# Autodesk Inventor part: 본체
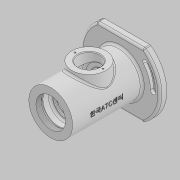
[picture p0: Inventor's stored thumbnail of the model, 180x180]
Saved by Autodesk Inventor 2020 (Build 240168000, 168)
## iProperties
Created: 2022-05
Part Number: 본체
Material: 일반
Document SubType Name: Modeling
Designer: User
Density: 1 g/cm^3
Appearance: 기본값
Author: User
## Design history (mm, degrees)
sketch "스케치1"
  geometry: L1 (-33.985, 47)-(33.985, 47); L2 (-33.985, -47)-(33.985, -47); A1 r 58 centre (0, 0) between (33.985, -47) and (33.985, 47); A2 r 58 centre (0, 0) between (-33.985, 47) and (-33.985, -47); 2 further points
  constraints: 4 end point, 4 point on circle, 3 vertical alignment, 2 centre point, 2 coincident, 2 horizontal, 1 midpoint
  dimensions: "d0" = 94 distance between parallel lines of L2 L1; "d2" = 58 radius of A1
extrude "돌출1" new body sketch "스케치1" distance "d3" = 10; taper "d4" = 0 deg
sketch "스케치2"
  geometry: C1 r 36 at (0, 0); 1 further point
  constraints: 1 centre point, 1 coincident
  dimensions: "d5" = 72 diameter of C1
extrude "돌출2" join sketch "스케치2" distance "d6" = 3; taper "d7" = 0 deg
sketch "스케치3"
  geometry: C1 r 32 at (0, 0); 1 further point
  constraints: 1 centre point, 1 coincident
  dimensions: "d8" = 64 diameter of C1
extrude "돌출3" join sketch "스케치3" distance "d9" = 102; taper "d10" = 0 deg
sketch "스케치4"
  geometry: L1 (0, 0)-(48, 0); L2 (0, 0)-(36.77, 30.854); L3 (0, 0)-(-36.77, -30.854); L4 (-48, 0)-(0, 0); C1 r 4 at (36.77, 30.854); C2 r 4 at (-36.77, -30.854); A1 r 48 centre (0, 0) between (48, 0) and (36.77, 30.854); A2 r 48 centre (0, 0) between (48, 0) and (36.77, 30.854); A3 r 52 centre (0, 0) between (52, 0) and (39.834, 33.425); A4 r 44 centre (0, 0) between (44, 0) and (33.706, 28.283); A5 r 4 centre (48, 0) between (44, 0) and (52, 0); A6 r 4 centre (36.77, 30.854) between (39.834, 33.425) and (33.706, 28.283); A7 r 48 centre (0, 0) between (-48, 0) and (-36.77, -30.854); A8 r 52 centre (0, 0) between (-52, 0) and (-39.834, -33.425); A9 r 44 centre (0, 0) between (-44, 0) and (-33.706, -28.283); A10 r 4 centre (-48, 0) between (-44, 0) and (-52, 0); A11 r 4 centre (-36.77, -30.854) between (-39.834, -33.425) and (-33.706, -28.283); A12 r 48 centre (0, 0) between (48, 0) and (36.77, 30.854); A13 r 50.25 centre (0, 0) between (50.25, 0) and (38.494, 32.3); A14 r 45.75 centre (0, 0) between (45.75, 0) and (35.047, 29.408); A15 r 2.25 centre (48, 0) between (45.75, 0) and (50.25, 0); A16 r 2.25 centre (36.77, 30.854) between (38.494, 32.3) and (35.047, 29.408); A17 r 48 centre (0, 0) between (-48, 0) and (-36.77, -30.854); A18 r 50.25 centre (0, 0) between (-50.25, 0) and (-38.494, -32.3); A19 r 45.75 centre (0, 0) between (-45.75, 0) and (-35.047, -29.408); A20 r 2.25 centre (-48, 0) between (-45.75, 0) and (-50.25, 0); A21 r 2.25 centre (-36.77, -30.854) between (-38.494, -32.3) and (-35.047, -29.408); 5 further points
  constraints: 44 point on circle, 23 centre point, 16 tangent, 8 end point, 7 coincident, 2 horizontal
  dimensions: "d11" = 96 diameter of A1; "d12" = 40 deg angle of L1 L2; "d13" = 4 radius of A6; "d14" = 40 deg angle of L3 L4; "d15" = 4 radius of A10; "d16" = 2.25 radius of A16; "d18" = 2.25 radius of A20; "d25" = 8 diameter of C1; "d26" = 8 diameter of C2
extrude "돌출4" cut sketch "스케치4" distance "d19" = 4.4; taper "d20" = 0 deg
extrude "돌출5" cut sketch "스케치4" distance "d21" = 4.4; taper "d22" = 0 deg
extrude "돌출6" cut sketch "스케치4" extent not by distance; stored distance "d23" = 0; taper "d24" = 0 deg
extrude "돌출7" cut sketch "스케치4" extent not by distance; stored distance "d27" = 102; taper "d28" = 0 deg
sketch "스케치5"
  geometry: L1 (-36, -3)-(36, -3) reference; L2 (0, -3)-(0, 104); L3 (0, 104)-(24, 104); L4 (24, 104)-(24, 101); L5 (24, 101)-(22.5, 101); L6 (22.5, 101)-(22.5, 93); L7 (19.5, 90)-(18.5, 90); L8 (17.5, 89)-(17.5, 87.75); L9 (17.5, 87.75)-(18.5, 87.75); L10 (18.5, 87.75)-(18.5, 86); L11 (18.5, 86)-(17.5, 86); L12 (17.5, 86)-(17.5, 76); L13 (18.5, 75)-(24, 75); L14 (27, 72)-(27, 40); L15 (24, 37)-(18.5, 37); L16 (17.5, 36)-(17.5, 26.6); L17 (16.9, 26)-(15, 26); L18 (15, 26)-(15, 24); L19 (12, 21)-(11, 21); L20 (11, 21)-(11, 18.3); L21 (11, 18.3)-(14.5, 18.3); L22 (15, 17.8)-(15, 11.7); L23 (15.404, 11)-(18.456, 11); L24 (20.897, 9.744)-(30, -3); L25 (18.5, 90)-(17.5, 89); L26 (18.5, 75)-(17.5, 76); L27 (18.5, 37)-(17.5, 36); L28 (15, 11.7)-(15.404, 11); A1 r 3 centre (24, 40) between (24, 37) and (27, 40); A2 r 3 centre (24, 72) between (27, 72) and (24, 75); A3 r 0.6 centre (16.9, 26.6) between (16.9, 26) and (17.5, 26.6); A4 r 0.5 centre (14.5, 17.8) between (15, 17.8) and (14.5, 18.3); A5 r 3 centre (12, 24) between (12, 21) and (15, 24); A6 r 3 centre (18.456, 8) between (20.897, 9.744) and (18.456, 11); A7 r 3 centre (19.5, 93) between (19.5, 90) and (22.5, 93); 12 further points
  constraints: 54 end point, 29 point on line, 17 perpendicular, 14 point on circle, 14 tangent, 7 centre point, 2 equal radius, 1 horizontal, 1 midpoint, 1 vertical
  dimensions: "d29" = 14 distance from line of L1 point (20, 11); "d32" = 7.3 distance of point (15, 18.3) point (15, 11); "d33" = 5 distance of L17.end point (15, 21); "d34" = 10 distance between parallel lines of L23 L19; "d35" = 11 distance of point (17.5, 37) point (17.5, 26); "d36" = 38 distance of point (27, 75) point (27, 37); "d37" = 11 distance of L11.end point (17.5, 75); "d38" = 1.75 distance of L9.end L10.end; "d39" = 4 distance between parallel lines of L11 L7; "d40" = 3 distance of L3.end L4.end; "d41" = 11 distance of L5.end point (22.5, 90); "d42" = 48 diameter of L4 L2; "d43" = 45 diameter of L6 L2; "d44" = 37 diameter of L10 L2; "d45" = 35 diameter of L12 L2; "d46" = 54 diameter of L14 L2; "d47" = 30 diameter of L18 L2; "d48" = 22 diameter of L20 L2; "d49" = 40 diameter of point (20, 11) L2; "d50" = 60 diameter of L24.end L2; "d51" = 1 distance of L7.end point (17.5, 90); "d52" = 45 deg angle of L7 L25; "d53" = 1 distance of L13.start point (17.5, 75); "d54" = 45 deg angle of L13 L26; "d55" = 3 radius of A1; "d56" = 1 distance of L15.end point (17.5, 37); "d57" = 45 deg angle of L15 L27; "d58" = 0.6 radius of A3; "d59" = 0.5 radius of A4; "d60" = 3 radius of A5 (derived); "d62" = 3 radius of A7 (derived); "d63" = 0.7 distance of L22.end point (15, 11); "d64" = 30 deg angle of L22 L28
revolve "회전1" sketch "스케치5" stored, may be unused: angle "d61" = 90 deg
sketch "스케치6"
  geometry: C1 r 32 at (0, 0) reference; 2 further points
  constraints: 1 coincident
hole "구멍1" sketch "스케치6" at (0, 0) diameter "d65" = 43.376; stored, may be unused: countersink angle "d69" = 90 deg, drill point angle "d71" = 118 deg; dims "d66" = 8, "d67" = 4, "d68" = 2, "d70" = 10
node "작업 평면1"
sketch "스케치7"
  geometry: L1 (32, 112)-(-32, 112) reference; C1 r 25 at (0, 56); C2 r 16 at (0, 56); 2 further points
  constraints: 2 centre point, 1 coincident, 1 midpoint, 1 vertical alignment
  dimensions: "d73" = 56 distance from line of L1 C1.centre; "d74" = 50 diameter of C1; "d75" = 32 diameter of C2
extrude "돌출8" join sketch "스케치7" stored distance "d76" = 4.4; taper "d77" = 5 deg
extrude "돌출9" cut sketch "스케치7" stored distance "d78" = 4.4; taper "d79" = 0 deg
node "작업 평면2"
sketch "스케치8" dims "d81" = 41
  geometry: L1 (-32, -56)-(32, -56) reference; L2 (33.985, 56)-(-33.985, 56) reference; L3 (0, 0)-(-20.5, 0); 3 further points
  constraints: 2 end point, 1 coincident, 1 horizontal, 1 horizontal alignment, 1 midpoint, 1 vertical alignment, 2 other
  dimensions: "d82" = 56 distance from line of L1 L3.start
hole "구멍2" sketch "스케치8" at (-20.5, 0) diameter "d83" = 2.459; stored, may be unused: countersink angle "d87" = 90 deg, drill point angle "d89" = 118 deg; dims "d84" = 6, "d85" = 4, "d86" = 2, "d88" = 8
node "작업 평면3"
sketch "스케치9"
  geometry: L1 (47, 0)-(-47, 0) reference; L2 (32, 112)-(-32, 112) reference; 3 further points
  constraints: 1 midpoint, 1 vertical alignment, 1 other
  dimensions: "d94" = 62 distance from line of L1 point (0, 62)
feature "엠보싱1" sketch "스케치9" dims "d0" = 94, "d11" = 96, "d12" = 40 deg, "d13" = 4, "d14" = 40 deg, "d15" = 4, "d16" = 2.25, "d18" = 2.25, "d25" = 8, "d26" = 8, "d95" = 0.5, "d96" = 0
chamfer "모따기1" distance "d97" = 1; stored, may be unused: second distance "d98" = 2, angle "d99" = 45 deg
fillet "모깎기1" dims "d100" = 3
fillet "모깎기2" dims "d101" = 3
fillet "모깎기3" dims "d102" = 3
fillet "모깎기4" dims "d103" = 3
chamfer "모따기2" distance "d104" = 1; stored, may be unused: second distance "d105" = 2, angle "d106" = 45 deg
node "솔리드1"
pattern_circular "원형 패턴1" dims angle "d91" = 360 deg
feature "A9D066F2-1C7D-4E18-AEED-F7BC21143FA4" dims "d65" = 43.376, "d66" = 8, "d67" = 4, "d68" = 2, "d69" = 90 deg, "d70" = 10, "d71" = 118 deg
other parameters: "d72" = 38, "d80" = 59, "d93" = 32
